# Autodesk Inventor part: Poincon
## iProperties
Author: Flavien MARTY
Shininess: 100.0
PropertySet Name: _Private Model Information
Created: 2001-10
Part Number: Poincon
Material: Par défaut
Document SubType Name: Modélisation
Designer: Flavien MARTY
Control State: 0
Master: False
Checked Out: False
PropertySet Name: Design Tracking Control
Density: 0.0
Volumn: 0.0
Area: 0.0
PropertySet Name: Model Information
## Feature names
1. Base1
